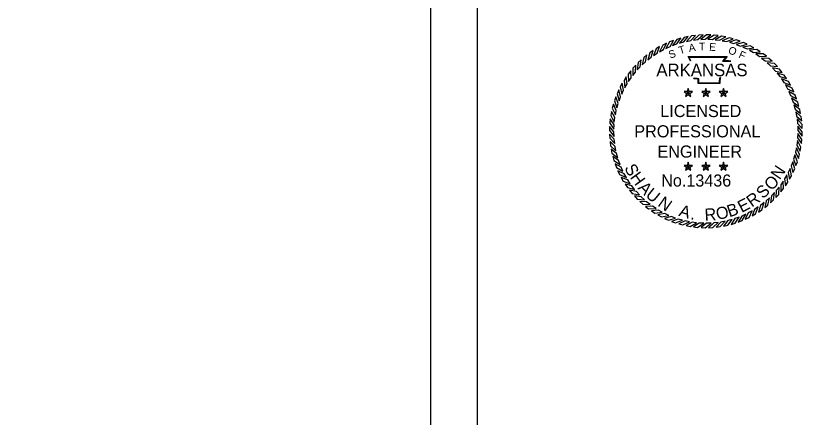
# Model space of a CAD drawing. Extents: x 0 to 38.1, y -1.4 to 22.
# Drawn here: x 28.28 to 38.02, y 10.32 to 15.29 of the extents above; entities that cross this region are included whole.
import ezdxf

# ---------------------------------------------------------------- set-up
doc = ezdxf.new("R2010")
doc.units = 0
doc.layers.add('1', color=7, linetype='Continuous')
doc.layers.add('G-ANNO-SYMB', color=7, linetype='Continuous')

msp = doc.modelspace()

# ---------------------------------------------------------------- linework, layer by layer
at = {"layer": '1'}
msp.add_line((33.4232, 0.5768), (33.4232, 21.4232), dxfattribs=at)
msp.add_lwpolyline([(34, 22), (0, 22), (0, 0), (34, 0)], close=True, dxfattribs=at)
at = {"layer": 'G-ANNO-SYMB'}
for points in [[(36.5136, 15.0122), (36.4643, 14.9977), (36.4132, 14.9219), (36.4653, 14.9407)], [(36.6049, 15.033), (36.5547, 15.0225), (36.4977, 14.9509), (36.5512, 14.9656)], [(36.6976, 15.0467), (36.6467, 15.0401), (36.5843, 14.9732), (36.6388, 14.9837)], [(36.7911, 15.0531), (36.7398, 15.0505), (36.6724, 14.9887), (36.7275, 14.9948)], [(36.8847, 15.0521), (36.8334, 15.0535), (36.7614, 14.9972), (36.8168, 14.999)], [(36.9781, 15.0437), (36.927, 15.0492), (36.8508, 14.9987), (36.9061, 14.9961)], [(37.0704, 15.0281), (37.02, 15.0375), (36.94, 14.9932), (36.995, 14.9863)], [(37.1613, 15.0052), (37.1118, 15.0186), (37.0285, 14.9807), (37.0828, 14.9695)], [(37.2501, 14.9753), (37.2017, 14.9926), (37.1158, 14.9613), (37.169, 14.9458)], [(36.2533, 14.9076), (36.2088, 14.882), (36.1768, 14.7964), (36.2231, 14.8268)], [(36.3372, 14.9492), (36.2909, 14.9272), (36.2522, 14.8444), (36.3008, 14.8711)], [(36.4242, 14.9842), (36.3762, 14.9659), (36.3312, 14.8863), (36.3817, 14.9091)], [(37.3362, 14.9386), (37.2894, 14.9595), (37.2013, 14.9351), (37.2532, 14.9155)], [(37.4193, 14.8951), (37.3742, 14.9197), (37.2845, 14.9023), (37.3346, 14.8787)], [(36.0965, 14.8052), (36.0566, 14.773), (36.0383, 14.6834), (36.0793, 14.7207)], [(36.1729, 14.8595), (36.1305, 14.8305), (36.1053, 14.7426), (36.1491, 14.7766)], [(37.4986, 14.8453), (37.4556, 14.8734), (37.3648, 14.863), (37.4129, 14.8356)], [(37.5738, 14.7895), (37.5332, 14.8208), (37.4418, 14.8176), (37.4876, 14.7864)], [(36.0246, 14.7452), (35.9873, 14.7099), (35.9762, 14.6191), (36.0141, 14.6596)], [(37.6444, 14.7278), (37.6064, 14.7623), (37.515, 14.7663), (37.5583, 14.7316)], [(37.7099, 14.6609), (37.6747, 14.6982), (37.5839, 14.7093), (37.6244, 14.6714)], [(35.8961, 14.609), (35.8647, 14.5684), (35.8679, 14.477), (35.8991, 14.5229)], [(35.9577, 14.6796), (35.9233, 14.6416), (35.9193, 14.5502), (35.9539, 14.5935)], [(37.77, 14.589), (37.7378, 14.629), (37.6482, 14.6472), (37.6855, 14.6062)], [(35.8402, 14.5338), (35.8122, 14.4909), (35.8225, 14.4), (35.85, 14.4482)], [(37.8243, 14.5126), (37.7953, 14.555), (37.7074, 14.5802), (37.7414, 14.5364)], [(37.8724, 14.4322), (37.8468, 14.4767), (37.7612, 14.5087), (37.7916, 14.4624)], [(35.7904, 14.4545), (35.7658, 14.4094), (35.7833, 14.3197), (35.8068, 14.3698)], [(37.914, 14.3483), (37.892, 14.3947), (37.8091, 14.4333), (37.8359, 14.3847)], [(35.747, 14.3715), (35.726, 14.3246), (35.7504, 14.2365), (35.77, 14.2884)], [(36.607, 14.3355), (36.5947, 14.3524), (36.5551, 14.3524), (36.5872, 14.3291)], [(36.607, 14.3355), (36.5872, 14.3291), (36.5749, 14.2914), (36.607, 14.3147)], [(36.607, 14.3355), (36.6192, 14.3524), (36.607, 14.39), (36.5947, 14.3524)], [(36.607, 14.3355), (36.6268, 14.3291), (36.6588, 14.3524), (36.6192, 14.3524)], [(36.607, 14.3355), (36.607, 14.3147), (36.639, 14.2914), (36.6268, 14.3291)], [(36.8252, 14.3355), (36.8129, 14.3524), (36.7733, 14.3524), (36.8053, 14.3291)], [(36.8252, 14.3355), (36.8053, 14.3291), (36.7931, 14.2914), (36.8252, 14.3147)], [(36.8252, 14.3355), (36.8374, 14.3524), (36.8252, 14.39), (36.8129, 14.3524)], [(36.8252, 14.3355), (36.845, 14.3291), (36.877, 14.3524), (36.8374, 14.3524)], [(36.8252, 14.3355), (36.8252, 14.3147), (36.8572, 14.2914), (36.845, 14.3291)], [(37.0433, 14.3355), (37.0311, 14.3524), (36.9915, 14.3524), (37.0235, 14.3291)], [(37.0433, 14.3355), (37.0235, 14.3291), (37.0113, 14.2914), (37.0433, 14.3147)], [(37.0433, 14.3355), (37.0556, 14.3524), (37.0433, 14.39), (37.0311, 14.3524)], [(37.0433, 14.3355), (37.0632, 14.3291), (37.0952, 14.3524), (37.0556, 14.3524)], [(37.0433, 14.3355), (37.0433, 14.3147), (37.0754, 14.2914), (37.0632, 14.3291)], [(37.9489, 14.2614), (37.9307, 14.3093), (37.8511, 14.3543), (37.8739, 14.3038)], [(35.7102, 14.2853), (35.693, 14.237), (35.7242, 14.151), (35.7397, 14.2043)], [(37.9769, 14.172), (37.9625, 14.2212), (37.8867, 14.2723), (37.9055, 14.2202)], [(35.6803, 14.1965), (35.6669, 14.147), (35.7048, 14.0637), (35.716, 14.118)], [(37.9978, 14.0806), (37.9873, 14.1308), (37.9157, 14.1878), (37.9304, 14.1343)], [(35.6574, 14.1056), (35.648, 14.0552), (35.6923, 13.9752), (35.6993, 14.0302)], [(38.0115, 13.9879), (38.0049, 14.0388), (37.938, 14.1012), (37.9484, 14.0468)], [(35.6418, 14.0133), (35.6363, 13.9622), (35.6868, 13.886), (35.6894, 13.9414)], [(38.0179, 13.8945), (38.0153, 13.9457), (37.9535, 14.0131), (37.9596, 13.958)], [(38.0169, 13.8008), (38.0183, 13.8521), (37.962, 13.9241), (37.9638, 13.8687)], [(35.6335, 13.9199), (35.632, 13.8687), (35.6883, 13.7966), (35.6865, 13.852)], [(35.6325, 13.8263), (35.635, 13.775), (35.6968, 13.7076), (35.6907, 13.7627)], [(38.0085, 13.7075), (38.014, 13.7585), (37.9635, 13.8347), (37.9609, 13.7794)], [(35.6388, 13.7328), (35.6454, 13.6819), (35.7123, 13.6195), (35.7019, 13.674)], [(37.9929, 13.6151), (38.0023, 13.6655), (37.958, 13.7455), (37.9511, 13.6905)], [(35.6525, 13.6401), (35.663, 13.5899), (35.7346, 13.533), (35.72, 13.5864)], [(37.97, 13.5242), (37.9834, 13.5738), (37.9455, 13.657), (37.9343, 13.6027)], [(35.6734, 13.5488), (35.6878, 13.4995), (35.7636, 13.4484), (35.7449, 13.5006)], [(37.9401, 13.4354), (37.9574, 13.4838), (37.9261, 13.5697), (37.9106, 13.5165)], [(35.7014, 13.4594), (35.7196, 13.4114), (35.7992, 13.3664), (35.7764, 13.4169)], [(36.607, 13.4219), (36.5947, 13.4387), (36.5551, 13.4387), (36.5872, 13.4154)], [(36.607, 13.4219), (36.6192, 13.4387), (36.607, 13.4764), (36.5947, 13.4387)], [(36.607, 13.4219), (36.6268, 13.4154), (36.6588, 13.4387), (36.6192, 13.4387)], [(36.8252, 13.4219), (36.8129, 13.4387), (36.7733, 13.4387), (36.8053, 13.4154)], [(36.8252, 13.4219), (36.8374, 13.4387), (36.8252, 13.4764), (36.8129, 13.4387)], [(36.8252, 13.4219), (36.845, 13.4154), (36.877, 13.4387), (36.8374, 13.4387)], [(37.0433, 13.4219), (37.0311, 13.4387), (36.9915, 13.4387), (37.0235, 13.4154)], [(37.0433, 13.4219), (37.0556, 13.4387), (37.0433, 13.4764), (37.0311, 13.4387)], [(37.0433, 13.4219), (37.0632, 13.4154), (37.0952, 13.4387), (37.0556, 13.4387)], [(37.9033, 13.3493), (37.9243, 13.3961), (37.8999, 13.4842), (37.8803, 13.4324)], [(35.7363, 13.3724), (35.7583, 13.3261), (35.8412, 13.2874), (35.8144, 13.336)], [(36.607, 13.4219), (36.5872, 13.4154), (36.5749, 13.3777), (36.607, 13.401)], [(36.607, 13.4219), (36.607, 13.401), (36.639, 13.3777), (36.6268, 13.4154)], [(36.8252, 13.4219), (36.8053, 13.4154), (36.7931, 13.3777), (36.8252, 13.401)], [(36.8252, 13.4219), (36.8252, 13.401), (36.8572, 13.3777), (36.845, 13.4154)], [(37.0433, 13.4219), (37.0235, 13.4154), (37.0113, 13.3777), (37.0433, 13.401)], [(37.0433, 13.4219), (37.0433, 13.401), (37.0754, 13.3777), (37.0632, 13.4154)], [(37.8599, 13.2663), (37.8845, 13.3113), (37.8671, 13.4011), (37.8435, 13.3509)], [(35.7779, 13.2885), (35.8035, 13.244), (35.8891, 13.212), (35.8587, 13.2583)], [(37.7542, 13.1117), (37.7856, 13.1523), (37.7824, 13.2437), (37.7512, 13.1979)], [(37.8101, 13.1869), (37.8382, 13.2299), (37.8278, 13.3207), (37.8004, 13.2726)], [(35.826, 13.2081), (35.855, 13.1658), (35.9429, 13.1405), (35.9089, 13.1843)], [(37.6926, 13.0411), (37.7271, 13.0792), (37.731, 13.1705), (37.6964, 13.1273)], [(35.8803, 13.1317), (35.9125, 13.0918), (36.0021, 13.0735), (35.9648, 13.1145)], [(35.9404, 13.0598), (35.9756, 13.0225), (36.0664, 13.0114), (36.026, 13.0493)], [(37.6257, 12.9756), (37.663, 13.0108), (37.6741, 13.1016), (37.6362, 13.0612)], [(36.0059, 12.9929), (36.044, 12.9585), (36.1353, 12.9545), (36.092, 12.9891)], [(37.4774, 12.8612), (37.5198, 12.8902), (37.545, 12.9781), (37.5012, 12.9441)], [(37.5538, 12.9155), (37.5937, 12.9477), (37.612, 13.0373), (37.571, 13)], [(36.0765, 12.9313), (36.1171, 12.9), (36.2085, 12.9031), (36.1627, 12.9343)], [(36.1517, 12.8754), (36.1947, 12.8474), (36.2855, 12.8577), (36.2374, 12.8852)], [(37.3131, 12.7715), (37.3594, 12.7935), (37.3981, 12.8764), (37.3495, 12.8497)], [(37.397, 12.8131), (37.4415, 12.8387), (37.4735, 12.9244), (37.4272, 12.8939)], [(36.231, 12.8256), (36.2761, 12.801), (36.3659, 12.8185), (36.3157, 12.8421)], [(36.3141, 12.7822), (36.3609, 12.7612), (36.449, 12.7856), (36.3972, 12.8052)], [(36.4002, 12.7454), (36.4486, 12.7282), (36.5345, 12.7594), (36.4813, 12.7749)], [(37.0454, 12.6877), (37.0956, 12.6982), (37.1526, 12.7698), (37.0991, 12.7552)], [(37.1367, 12.7086), (37.186, 12.723), (37.2371, 12.7989), (37.185, 12.7801)], [(37.2262, 12.7366), (37.2741, 12.7549), (37.3191, 12.8345), (37.2686, 12.8116)], [(36.489, 12.7155), (36.5386, 12.7021), (36.6218, 12.74), (36.5675, 12.7513)], [(36.5799, 12.6927), (36.6303, 12.6832), (36.7103, 12.7275), (36.6553, 12.7345)], [(36.6723, 12.677), (36.7233, 12.6715), (36.7995, 12.722), (36.7442, 12.7246)], [(36.7656, 12.6687), (36.8169, 12.6672), (36.8889, 12.7235), (36.8335, 12.7218)], [(36.8593, 12.6677), (36.9105, 12.6702), (36.9779, 12.732), (36.9228, 12.7259)], [(36.9527, 12.674), (37.0036, 12.6806), (37.066, 12.7475), (37.0115, 12.7371)]]:
    msp.add_lwpolyline(points, close=True, dxfattribs=at)
for points in [[(36.634, 14.7264), (36.6062, 14.7866), (37.0875, 14.7869), (37.0472, 14.7364), (37.0799, 14.7368), (37.1073, 14.7371), (37.1345, 14.7342)], [(36.6409, 14.7296), (36.6181, 14.779), (37.0716, 14.7793), (37.0313, 14.7285), (37.08, 14.7292), (37.1069, 14.7295), (37.1337, 14.7266)], [(37.0116, 14.5247), (37.0034, 14.518), (37.0007, 14.508), (36.998, 14.4831), (36.998, 14.4498), (36.7293, 14.4498), (36.7293, 14.4947), (36.7293, 14.5047), (36.7184, 14.508), (36.6802, 14.508), (36.6734, 14.5184)], [(37.0068, 14.5306), (36.9967, 14.5224), (36.9932, 14.5094), (36.9903, 14.4835), (36.9903, 14.4574), (36.7369, 14.4574), (36.7369, 14.4947), (36.7369, 14.5103), (36.7195, 14.5156), (36.6843, 14.5156), (36.6798, 14.5226)]]:
    msp.add_lwpolyline(points, dxfattribs=at)

# ---------------------------------------------------------------- texts
for s, height, rotation, p in [('T', 0.0949, 16.90148, (36.5041, 14.8121)), ('A', 0.0949, 8.67877, (36.6193, 14.8422)), ('T', 0.0949, 1.47887, (36.7419, 14.8611)), ('E', 0.0949, 356.67203, (36.8634, 14.8582)), ('O', 0.0949, 341.2218, (37.0939, 14.8257)), ('S', 0.0949, 19.77256, (36.3833, 14.7579)), ('F', 0.0949, 335.36282, (37.2219, 14.7756)), ('ARKANSAS', 0.15494, 360, (36.2128, 14.542)), ('LICENSED', 0.15, 360, (36.2609, 14.0362)), ('PROFESSIONAL', 0.150001, 360, (35.9394, 13.7854)), ('ENGINEER', 0.15, 360, (36.2252, 13.5345)), ('S', 0.15, 298.16364, (35.8116, 13.4084)), ('N', 0.15, 56.10067, (37.7399, 13.2517)), ('H', 0.15, 305.61905, (35.8799, 13.2909)), ('No.13436', 0.14941, 360, (36.2725, 13.1769)), ('O', 0.15, 44.77573, (37.6358, 13.1166)), ('A', 0.15, 313.44722, (35.9752, 13.1539)), ('U', 0.15, 320.90262, (36.0687, 13.0561)), ('S', 0.15, 43.48784, (37.5327, 13.0171)), ('N', 0.15, 324.93262, (36.2199, 12.9444)), ('R', 0.15, 35.65967, (37.3948, 12.9152)), ('B', 0.15, 18.88501, (37.1165, 12.7946)), ('E', 0.15, 27.83149, (37.268, 12.8488)), ('A', 0.15, 343.09908, (36.4813, 12.8157)), ('R', 0.15, 3.22866, (36.8127, 12.753)), ('O', 0.15, 11.42961, (36.9662, 12.7627)), ('.', 0.15, 351.30002, (36.6288, 12.772))]:
    msp.add_text(s, height=height, rotation=rotation, dxfattribs=at).set_placement(p)

doc.saveas('drawing.dxf')
